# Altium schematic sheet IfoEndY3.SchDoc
size C; Engineer: Daniel Sigg; DocumentNumber: 7; SheetNumber: 31; SheetTotal: 33
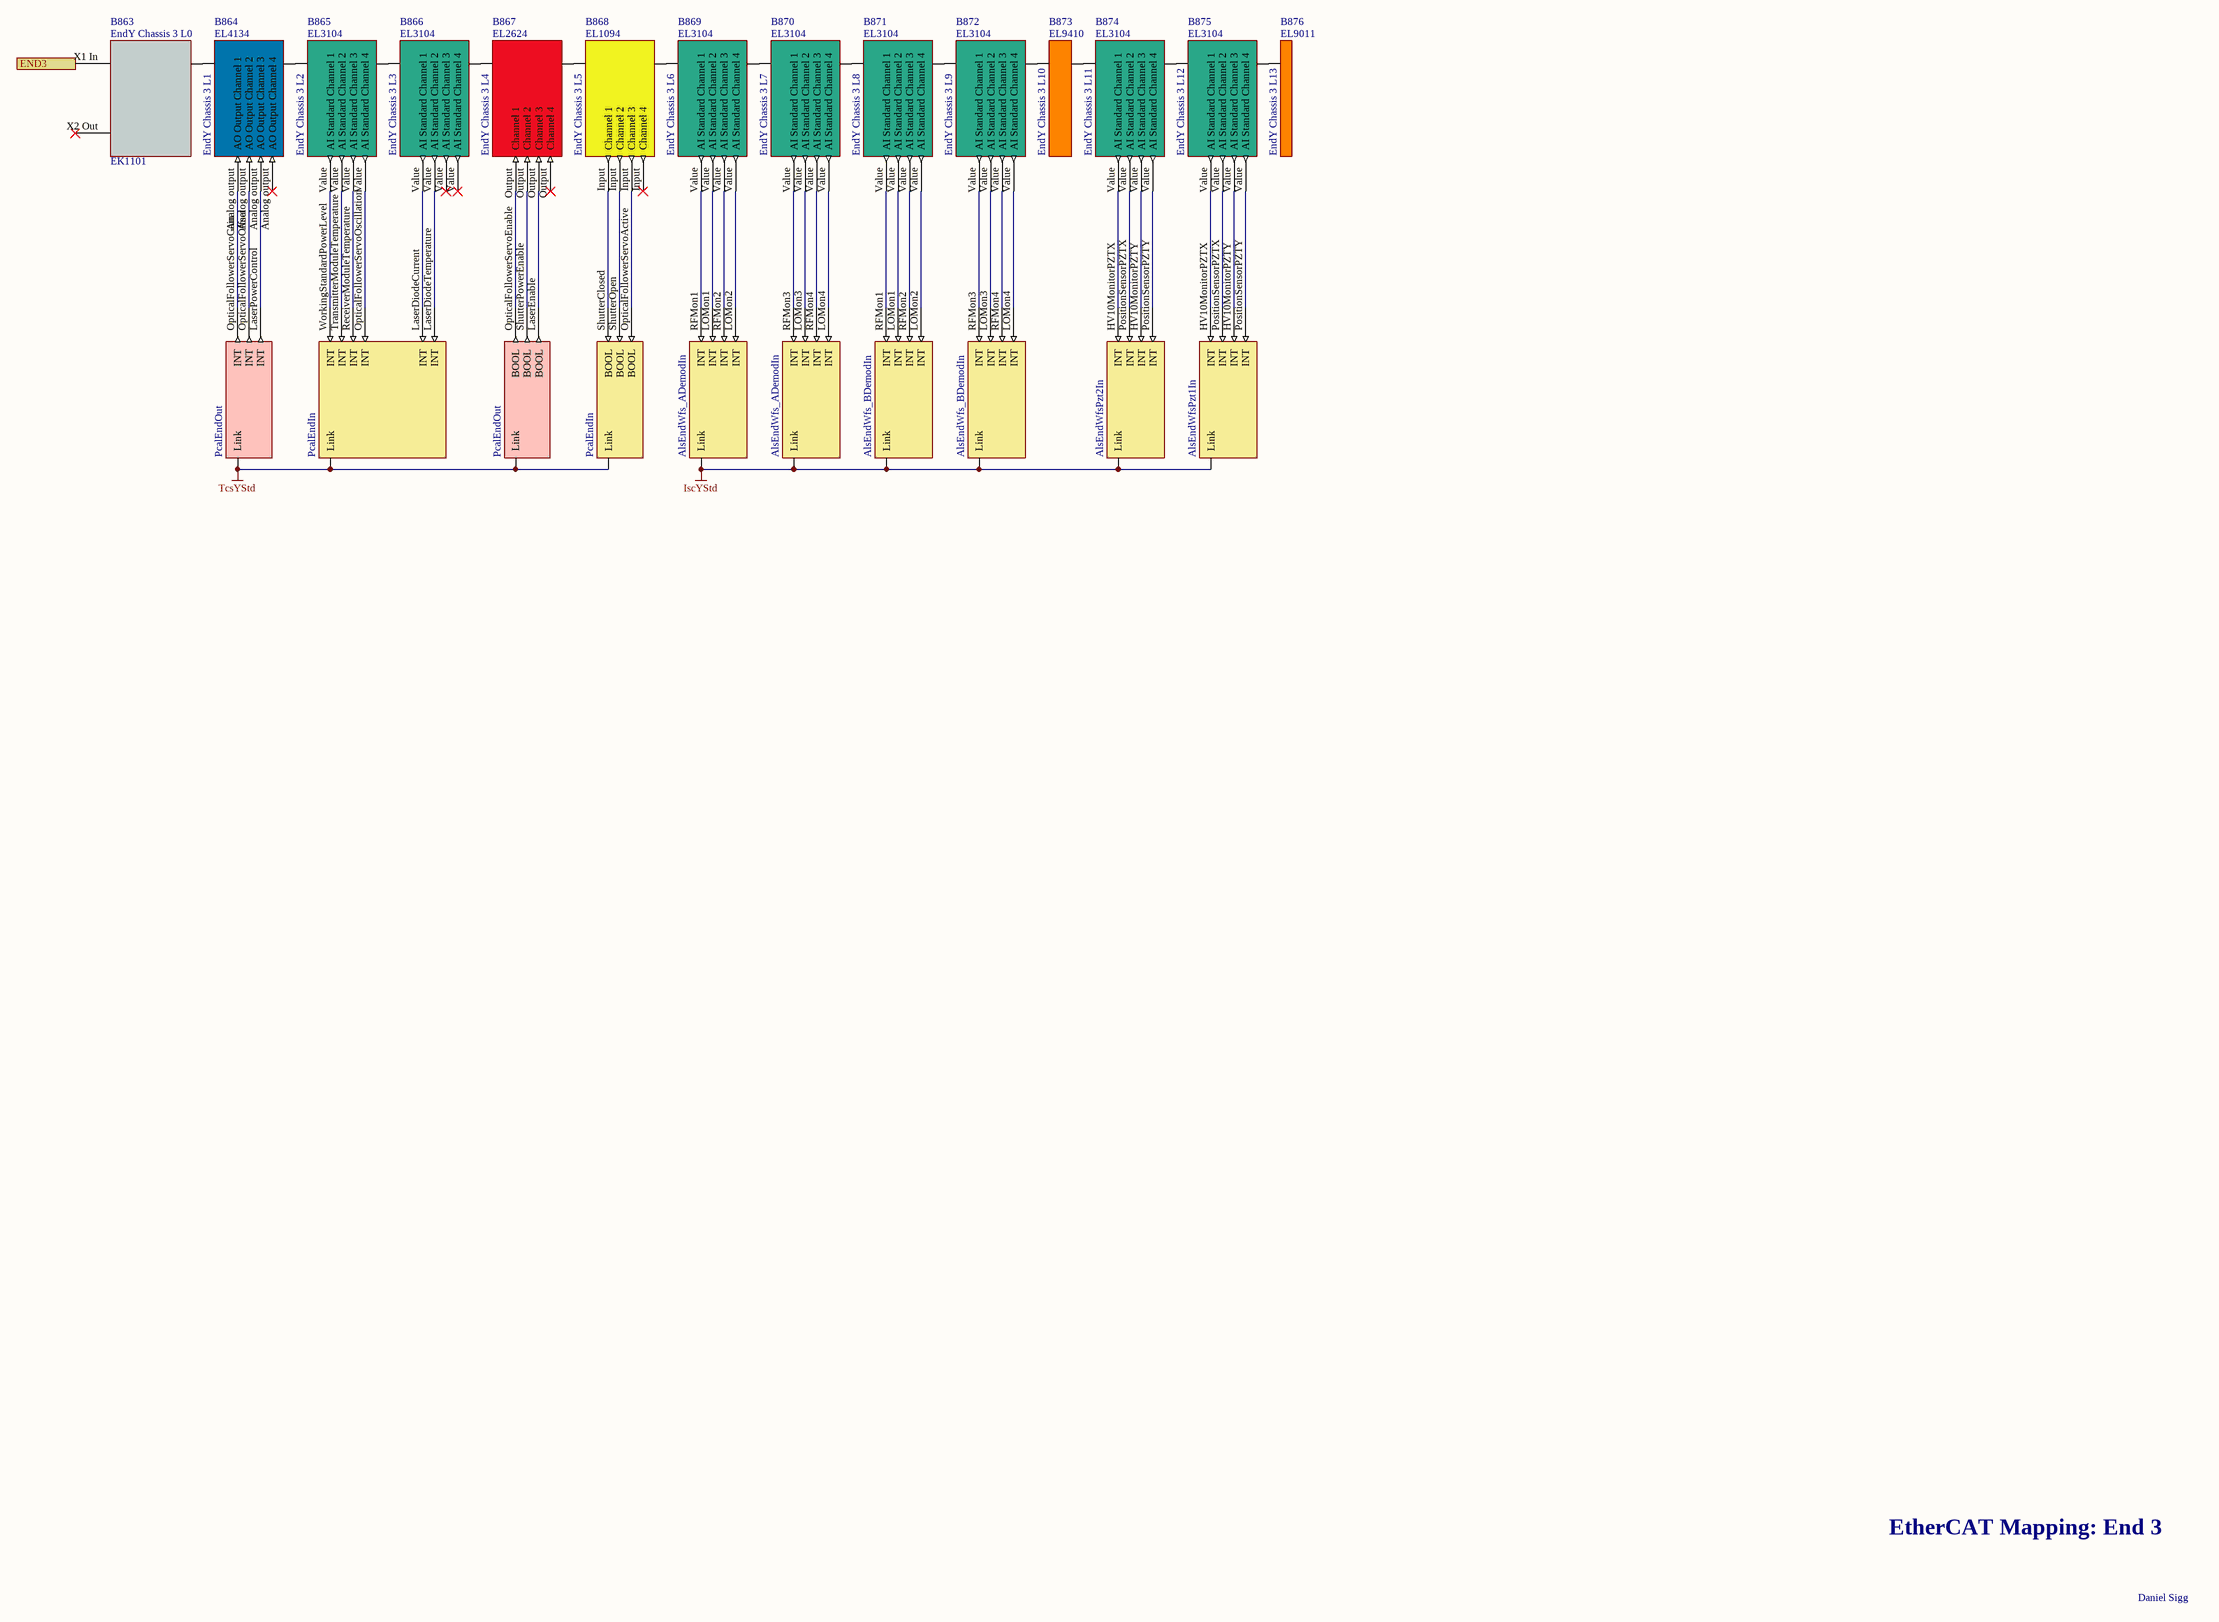
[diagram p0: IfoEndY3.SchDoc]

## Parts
B863  EndY Chassis 3 L0  Part Number: EK1101
B864  EndY Chassis 3 L1  Part Number: EL4134  (mechanical)
B865  EndY Chassis 3 L2  Part Number: EL3104  (mechanical)
B866  EndY Chassis 3 L3  Part Number: EL3104  (mechanical)
B867  EndY Chassis 3 L4  Part Number: EL2624  (mechanical)
B868  EndY Chassis 3 L5  Part Number: EL1094  (mechanical)
B869  EndY Chassis 3 L6  Part Number: EL3104  (mechanical)
B870  EndY Chassis 3 L7  Part Number: EL3104  (mechanical)
B871  EndY Chassis 3 L8  Part Number: EL3104  (mechanical)
B872  EndY Chassis 3 L9  Part Number: EL3104  (mechanical)
B873  EndY Chassis 3 L10  Part Number: EL9410  (mechanical)
B874  EndY Chassis 3 L11  Part Number: EL3104  (mechanical)
B875  EndY Chassis 3 L12  Part Number: EL3104  (mechanical)
B876  EndY Chassis 3 L13  Part Number: EL9011  (mechanical)
V678  PcalEndOut  (parts A,B of 2)  (no BOM)
V679  PcalEndIn  (parts A,B of 2)  (no BOM)
V682  AlsEndWfs_ADemodIn  (parts A,B of 2)  (no BOM)
V683  AlsEndWfs_BDemodIn  (parts A,B of 2)  (no BOM)
V684  AlsEndWfsPzt2In  (no BOM)
V685  AlsEndWfsPzt1In  (no BOM)

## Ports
END3

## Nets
IscYStd: V682.0(Link) V682.1(Link) V683.0(Link) V683.1(Link) V684.0(Link) V685.0(Link)
TcsYStd: V678.0(Link) V678.1(Link) V679.0(Link) V679.1(Link)
END3: B863.X1_In(A) ; port END3
NetB863_Ebus: B863.Ebus(B) B864.Ebus(A)
NetB864_Analog output: B864.Analog_output(AO_Output_Channel_1) V678.OpticalFollowerServoGain(INT)
NetB864_Analog output: B864.Analog_output(AO_Output_Channel_2) V678.OpticalFollowerServoOffset(INT)  [a separate net that carries the same name]
NetB864_Analog output: B864.Analog_output(AO_Output_Channel_3) V678.LaserPowerControl(INT)  [a separate net that carries the same name]
NetB864_Ebus: B864.Ebus(B) B865.Ebus(A)
NetB865_Ebus: B865.Ebus(B) B866.Ebus(A)
NetB865_Value: B865.Value(AI_Standard_Channel_1) V679.WorkingStandardPowerLevel(INT)
NetB865_Value: B865.Value(AI_Standard_Channel_2) V679.TransmitterModuleTemperature(INT)  [a separate net that carries the same name]
NetB865_Value: B865.Value(AI_Standard_Channel_3) V679.ReceiverModuleTemperature(INT)  [a separate net that carries the same name]
NetB865_Value: B865.Value(AI_Standard_Channel_4) V679.OpticalFollowerServoOscillation(INT)  [a separate net that carries the same name]
NetB866_Ebus: B866.Ebus(B) B867.Ebus(A)
NetB866_Value: B866.Value(AI_Standard_Channel_1) V679.LaserDiodeCurrent(INT)
NetB866_Value: B866.Value(AI_Standard_Channel_2) V679.LaserDiodeTemperature(INT)  [a separate net that carries the same name]
NetB867_Ebus: B867.Ebus(B) B868.Ebus(A)
NetB867_Output: B867.Output(Channel_1) V678.OpticalFollowerServoEnable(BOOL)
NetB867_Output: B867.Output(Channel_2) V678.ShutterPowerEnable(BOOL)  [a separate net that carries the same name]
NetB867_Output: B867.Output(Channel_3) V678.LaserEnable(BOOL)  [a separate net that carries the same name]
NetB868_Ebus: B868.Ebus(B) B869.Ebus(A)
NetB868_Input: B868.Input(Channel_1) V679.ShutterClosed(BOOL)
NetB868_Input: B868.Input(Channel_2) V679.ShutterOpen(BOOL)  [a separate net that carries the same name]
NetB868_Input: B868.Input(Channel_3) V679.OpticalFollowerServoActive(BOOL)  [a separate net that carries the same name]
NetB869_Ebus: B869.Ebus(B) B870.Ebus(A)
NetB869_Value: B869.Value(AI_Standard_Channel_1) V682.RFMon1(INT)
NetB869_Value: B869.Value(AI_Standard_Channel_2) V682.LOMon1(INT)  [a separate net that carries the same name]
NetB869_Value: B869.Value(AI_Standard_Channel_3) V682.RFMon2(INT)  [a separate net that carries the same name]
NetB869_Value: B869.Value(AI_Standard_Channel_4) V682.LOMon2(INT)  [a separate net that carries the same name]
NetB870_Ebus: B870.Ebus(B) B871.Ebus(A)
NetB870_Value: B870.Value(AI_Standard_Channel_1) V682.RFMon3(INT)
NetB870_Value: B870.Value(AI_Standard_Channel_2) V682.LOMon3(INT)  [a separate net that carries the same name]
NetB870_Value: B870.Value(AI_Standard_Channel_3) V682.RFMon4(INT)  [a separate net that carries the same name]
NetB870_Value: B870.Value(AI_Standard_Channel_4) V682.LOMon4(INT)  [a separate net that carries the same name]
NetB871_Ebus: B871.Ebus(B) B872.Ebus(A)
NetB871_Value: B871.Value(AI_Standard_Channel_1) V683.RFMon1(INT)
NetB871_Value: B871.Value(AI_Standard_Channel_2) V683.LOMon1(INT)  [a separate net that carries the same name]
NetB871_Value: B871.Value(AI_Standard_Channel_3) V683.RFMon2(INT)  [a separate net that carries the same name]
NetB871_Value: B871.Value(AI_Standard_Channel_4) V683.LOMon2(INT)  [a separate net that carries the same name]
NetB872_Ebus: B872.Ebus(B) B873.Ebus(A)
NetB872_Value: B872.Value(AI_Standard_Channel_1) V683.RFMon3(INT)
NetB872_Value: B872.Value(AI_Standard_Channel_2) V683.LOMon3(INT)  [a separate net that carries the same name]
NetB872_Value: B872.Value(AI_Standard_Channel_3) V683.RFMon4(INT)  [a separate net that carries the same name]
NetB872_Value: B872.Value(AI_Standard_Channel_4) V683.LOMon4(INT)  [a separate net that carries the same name]
NetB873_Ebus: B873.Ebus(B) B874.Ebus(A)
NetB874_Ebus: B874.Ebus(B) B875.Ebus(A)
NetB874_Value: B874.Value(AI_Standard_Channel_1) V684.HV10MonitorPZTX(INT)
NetB874_Value: B874.Value(AI_Standard_Channel_2) V684.PositionSensorPZTX(INT)  [a separate net that carries the same name]
NetB874_Value: B874.Value(AI_Standard_Channel_3) V684.HV10MonitorPZTY(INT)  [a separate net that carries the same name]
NetB874_Value: B874.Value(AI_Standard_Channel_4) V684.PositionSensorPZTY(INT)  [a separate net that carries the same name]
NetB875_Ebus: B875.Ebus(B) B876.Ebus(A)
NetB875_Value: B875.Value(AI_Standard_Channel_1) V685.HV10MonitorPZTX(INT)
NetB875_Value: B875.Value(AI_Standard_Channel_2) V685.PositionSensorPZTX(INT)  [a separate net that carries the same name]
NetB875_Value: B875.Value(AI_Standard_Channel_3) V685.HV10MonitorPZTY(INT)  [a separate net that carries the same name]
NetB875_Value: B875.Value(AI_Standard_Channel_4) V685.PositionSensorPZTY(INT)  [a separate net that carries the same name]

Not connected (* = marked no-connect by the designer): B863 X2 Out(C)*

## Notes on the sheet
- EtherCAT Mapping: End 3
- Daniel Sigg

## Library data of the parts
B863 = CouplerEK1101: EtherCAT Coupler; Rail: Left; BoxNextB: RTJVESXI; BoxPrev: FUNVNSJV; PortPrevFull: 1088/C; PortPrevShort: C 'X2 Out'; Fullname: TIID^End Y (EtherCAT)^EndY Link L0 (EK1501-0010)^EndY Link L6 (EK1521)^EndY Chassis 3 L0 (EK1101); BoxPorts: Junction; BoxAddr: 1101; Disabled: False
B864 = TerminalEL4134: EtherCAT Terminal EL4134 4-chn Analog Ouput; Rail: Left; BoxNextB: EDKGMHJS; BoxPrev: YFCVOVJW; PortPrevFull: 1101/B; PortPrevShort: B; Fullname: TIID^End Y (EtherCAT)^EndY Link L0 (EK1501-0010)^EndY Link L6 (EK1521)^EndY Chassis 3 L0 (EK1101)^EndY Chassis 3 L1 (EL4134); BoxAddr: 1102; Disabled: False
B865 = TerminalEL3104: EtherCAT Terminal EL3104 4-chn Analog Input; Rail: Left; BoxNextB: WPQDJUME; BoxPrev: RTJVESXI; PortPrevFull: 1102/B; PortPrevShort: B; Fullname: TIID^End Y (EtherCAT)^EndY Link L0 (EK1501-0010)^EndY Link L6 (EK1521)^EndY Chassis 3 L0 (EK1101)^EndY Chassis 3 L2 (EL3104); BoxAddr: 1103; Disabled: False
B866 = TerminalEL3104: EtherCAT Terminal EL3104 4-chn Analog Input; Rail: Left; BoxNextB: XTBTIPST; BoxPrev: EDKGMHJS; PortPrevFull: 1103/B; PortPrevShort: B; Fullname: TIID^End Y (EtherCAT)^EndY Link L0 (EK1501-0010)^EndY Link L6 (EK1521)^EndY Chassis 3 L0 (EK1101)^EndY Chassis 3 L3 (EL3104); BoxAddr: 1104; Disabled: False
B867 = TerminalEL2624: EtherCAT Terminal EL2624 4-channel relay output terminal 125 V AC/30 V DC; Rail: Left; BoxNextB: CDABDOMD; BoxPrev: WPQDJUME; PortPrevFull: 1104/B; PortPrevShort: B; Fullname: TIID^End Y (EtherCAT)^EndY Link L0 (EK1501-0010)^EndY Link L6 (EK1521)^EndY Chassis 3 L0 (EK1101)^EndY Chassis 3 L4 (EL2624); BoxAddr: 1105; Disabled: False
B868 = TerminalEL1094: EtherCAT Terminal EL1094 4-channel digital input terminal 24 V DC, switching to negative potential; Rail: Left; BoxNextB: HWOARXEL; BoxPrev: XTBTIPST; PortPrevFull: 1105/B; PortPrevShort: B; Fullname: TIID^End Y (EtherCAT)^EndY Link L0 (EK1501-0010)^EndY Link L6 (EK1521)^EndY Chassis 3 L0 (EK1101)^EndY Chassis 3 L5 (EL1094); BoxAddr: 1106; Disabled: False
B869 = TerminalEL3104: EtherCAT Terminal EL3104 4-chn Analog Input; Rail: Left; BoxNextB: FNVPWBXG; BoxPrev: CDABDOMD; PortPrevFull: 1106/B; PortPrevShort: B; Fullname: TIID^End Y (EtherCAT)^EndY Link L0 (EK1501-0010)^EndY Link L6 (EK1521)^EndY Chassis 3 L0 (EK1101)^EndY Chassis 3 L6 (EL3104); BoxAddr: 1107; Disabled: False
B870 = TerminalEL3104: EtherCAT Terminal EL3104 4-chn Analog Input; Rail: Left; BoxNextB: ICTEJMQO; BoxPrev: HWOARXEL; PortPrevFull: 1107/B; PortPrevShort: B; Fullname: TIID^End Y (EtherCAT)^EndY Link L0 (EK1501-0010)^EndY Link L6 (EK1521)^EndY Chassis 3 L0 (EK1101)^EndY Chassis 3 L7 (EL3104); BoxAddr: 1108; Disabled: False
B871 = TerminalEL3104: EtherCAT Terminal EL3104 4-chn Analog Input; Rail: Left; BoxNextB: KRHKWTDQ; BoxPrev: FNVPWBXG; PortPrevFull: 1108/B; PortPrevShort: B; Fullname: TIID^End Y (EtherCAT)^EndY Link L0 (EK1501-0010)^EndY Link L6 (EK1521)^EndY Chassis 3 L0 (EK1101)^EndY Chassis 3 L8 (EL3104); BoxAddr: 1109; Disabled: False
B872 = TerminalEL3104: EtherCAT Terminal EL3104 4-chn Analog Input; Rail: Left; BoxNextB: VRPATLRK; BoxPrev: ICTEJMQO; PortPrevFull: 1109/B; PortPrevShort: B; Fullname: TIID^End Y (EtherCAT)^EndY Link L0 (EK1501-0010)^EndY Link L6 (EK1521)^EndY Chassis 3 L0 (EK1101)^EndY Chassis 3 L9 (EL3104); BoxAddr: 1110; Disabled: False
B873 = TerminalEL9410: EtherCAT Terminal EL9410 Power; Rail: Left; BoxNextB: WQHOYDBG; BoxPrev: KRHKWTDQ; PortPrevFull: 1110/B; PortPrevShort: B; Fullname: TIID^End Y (EtherCAT)^EndY Link L0 (EK1501-0010)^EndY Link L6 (EK1521)^EndY Chassis 3 L0 (EK1101)^EndY Chassis 3 L10 (EL9410); BoxAddr: 1111; Disabled: False
B874 = TerminalEL3104: EtherCAT Terminal EL3104 4-chn Analog Input; Rail: Left; BoxNextB: WQSRVVLN; BoxPrev: VRPATLRK; PortPrevFull: 1111/B; PortPrevShort: B; Fullname: TIID^End Y (EtherCAT)^EndY Link L0 (EK1501-0010)^EndY Link L6 (EK1521)^EndY Chassis 3 L0 (EK1101)^EndY Chassis 3 L11 (EL3104); BoxAddr: 1112; Disabled: False
B875 = TerminalEL3104: EtherCAT Terminal EL3104 4-chn Analog Input; Rail: Left; BoxNextB: REASFWIS; BoxPrev: WQHOYDBG; PortPrevFull: 1112/B; PortPrevShort: B; Fullname: TIID^End Y (EtherCAT)^EndY Link L0 (EK1501-0010)^EndY Link L6 (EK1521)^EndY Chassis 3 L0 (EK1101)^EndY Chassis 3 L12 (EL3104); BoxAddr: 1113; Disabled: False
B876 = TerminalEL9011: EtherCAT Terminal EL9011 End; BoxType: TerminalPassive; Rail: Left; BoxPrev: WQSRVVLN; PortPrevShort: B; Fullname: TIID^End Y (EtherCAT)^EndY Link L0 (EK1501-0010)^EndY Link L6 (EK1521)^EndY Chassis 3 L0 (EK1101)^EndY Chassis 3 L13 (EL9011); Disabled: False
V678 = Pcal_PcalOutStruct: PcalOutStruct; BoxType: Variable; Instance: H1TcsEndY Instance; PLC: H1TcsEndY; Task: TcsEStd
V679 = Pcal_PcalInStruct: PcalInStruct; BoxType: Variable; Instance: H1TcsEndY Instance; PLC: H1TcsEndY; Task: TcsEStd
V682 V683 = Demodulator_DemodulatorQuadInStruct: DemodulatorQuadInStruct; BoxType: Variable; Instance: H1IscEndY Instance; PLC: H1IscEndY; Task: IscEStd
V684 V685 = PZTMirror_PZTMirrorInStruct: PZTMirrorInStruct; BoxType: Variable; Instance: H1IscEndY Instance; PLC: H1IscEndY; Task: IscEStd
